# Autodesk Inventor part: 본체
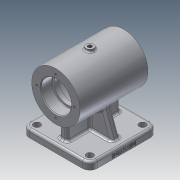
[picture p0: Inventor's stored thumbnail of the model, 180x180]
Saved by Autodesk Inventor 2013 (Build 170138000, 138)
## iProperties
Created: 2019-06
Part Number: 본체
Material: 알루미늄 6061
Document SubType Name: Modeling
Designer: user
Density: 2.71 g/cm^3
Mass: 612.592 g
Surface Area: 621.749 cm^2
Volume: 226.049 cm^3
Author: user
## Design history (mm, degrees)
sketch "스케치1"
  geometry: C1 r 32 at (0, 0); 1 further point
  constraints: 1 centre point, 1 coincident
  dimensions: "d0" = 64 diameter of C1
extrude "돌출1" new body sketch "스케치1" stored distance "d1" = 90; taper "d2" = 0 deg
sketch "스케치2"
  geometry: L1 (32, 45)-(-32, 45) reference; L2 (-32, -45)-(32, -45) reference; L3 (0, 45)-(0, -45); L4 (20, 45)-(20, 30); L5 (20, 30)-(17, 30); L6 (17, 30)-(17, 24); L7 (17, 24)-(25, 24); L8 (25, 24)-(25, -24); L9 (25, -24)-(17, -24); L10 (17, -24)-(17, -30); L11 (17, -30)-(20, -30); L12 (20, -30)-(20, -45); 1 further point
  constraints: 20 end point, 5 perpendicular, 4 parallel, 2 midpoint, 2 point on line
  dimensions: "d3" = 15 distance of L4.start L4.end; "d5" = 15 distance of L11.end L12.end; "d6" = 6 distance of L5.end L6.end; "d7" = 6 distance of L9.end L10.end; "d8" = 40 diameter of L4 L3; "d9" = 40 diameter of L12 L3; "d10" = 50 diameter of L8 L3; "d11" = 34 diameter of L6 L3; "d12" = 34 diameter of L10 L3
revolve "회전1" sketch "스케치2" stored, may be unused: angle "d13" = 90 deg
chamfer "모따기1" distance "d14" = 1; stored, may be unused: second distance "d15" = 2, angle "d16" = 45 deg
fillet "모깎기1" dims "d17" = 3
fillet "모깎기2" dims "d18" = 0.6
sketch "스케치3"
  geometry: L1 (0, 0)-(0, 25); C1 r 21 at (0, 0) reference; 1 further point
  constraints: 2 end point, 1 coincident, 1 vertical
  dimensions: "d19" = 25 distance of L1.start L1.end
hole "구멍1" sketch "스케치3" at (0, 25) diameter "d20" = 3.242; stored, may be unused: countersink angle "d24" = 90 deg, drill point angle "d26" = 118 deg; dims "d21" = 7, "d22" = 4, "d23" = 2, "d25" = 9
node "작업 평면1"
sketch "스케치4"
  geometry: L1 (45, -45)-(-45, -45); L2 (-45, -45)-(-45, 45); L3 (-45, 45)-(45, 45); L4 (45, 45)-(45, -45); L5 (45, -45)-(-45, 45); L6 (-45, -45)-(45, 45); 1 further point
  constraints: 12 end point, 2 midpoint, 2 parallel, 1 horizontal, 1 perpendicular
  dimensions: "d31" = 90 distance of L2.end L3.end; "d32" = 90 distance of L1.end L2.end
extrude "돌출2" join sketch "스케치4" distance "d33" = 10; taper "d34" = 0 deg
fillet "모깎기3" dims "d35" = 10
sketch "스케치5"
  geometry: A1 r 10 centre (-35, -35) between (-45, -35) and (-35, -45) reference; A2 r 10 centre (35, -35) between (35, -45) and (45, -35) reference; A3 r 10 centre (35, 35) between (45, 35) and (35, 45) reference; A4 r 10 centre (-35, 35) between (-35, 45) and (-45, 35) reference; 5 further points
  constraints: 4 coincident
hole "구멍2" sketch "스케치5" at (-35, 35), (35, 35), (35, -35), (-35, -35) diameter "d36" = 9; stored, may be unused: countersink angle "d40" = 90 deg, drill point angle "d42" = 118 deg; dims "d37" = 7, "d38" = 4, "d39" = 2, "d41" = 9
sketch "스케치6"
  geometry: L1 (5, -35)-(-5, -35); L2 (-5, -35)-(-5, 35); L3 (-5, 35)-(5, 35); L4 (5, 35)-(5, -35); L5 (5, -35)-(-5, 35); L6 (-5, -35)-(5, 35); 1 further point
  constraints: 12 end point, 2 midpoint, 2 parallel, 1 horizontal, 1 perpendicular
  dimensions: "d43" = 10 distance of L2.end L3.end; "d44" = 70 distance of L1.end L2.end
extrude "돌출3" join sketch "스케치6" stored distance "d45" = 10; taper "d46" = 0 deg
sketch "스케치7"
  geometry: L1 (35, -55)-(-35, -55) reference; L2 (23.058, -22.189)-(35, -55); L3 (45, -55)-(45, -65) reference; 2 further points
  constraints: 2 end point, 1 point on line, 2 other
  dimensions: "d47" = 110 deg angle of L1 L2; "d48" = 10 distance of L3.start L2.end
feature "리브1" sketch "스케치7" dims "d49" = 1, "d50" = 10, "d51" = 0, "d52" = 0, "d53" = 1, "d54" = 1
node "작업 평면2"
sketch "스케치8"
  geometry: C1 r 5 at (0, 0); 1 further point
  constraints: 1 centre point, 1 coincident
  dimensions: "d56" = 10 diameter of C1
extrude "돌출4" join sketch "스케치8" stored distance "d57" = 10; taper "d58" = 0 deg
sketch "스케치9"
  geometry: C1 r 5 at (0, 0) reference; 1 further point
  constraints: 1 coincident
hole "구멍3" sketch "스케치9" at (0, 0) diameter "d59" = 5.188; stored, may be unused: countersink angle "d63" = 90 deg, drill point angle "d65" = 118 deg; dims "d60" = 20, "d61" = 4, "d62" = 2, "d64" = 9
fillet "모깎기4" dims "d66" = 2
sketch "스케치11"
  geometry: L1 (40, -40)-(-40, -40); L2 (-40, -40)-(-40, 40); L3 (-40, 40)-(40, 40); L4 (40, 40)-(40, -40); C1 r 4.5 at (-35, 35) reference; C2 r 4.5 at (35, -35) reference; C3 r 4.5 at (-35, -35) reference; C4 r 4.5 at (35, 35) reference; 3 further points
  constraints: 8 end point, 2 midpoint, 2 parallel, 1 horizontal, 1 horizontal alignment, 1 perpendicular, 1 vertical alignment
  dimensions: "d73" = 80 distance of L2.end L3.end; "d74" = 80 distance of L1.end L2.end
extrude "돌출5" cut sketch "스케치11" distance "d76" = 5; taper "d77" = 0 deg
sketch "스케치12"
  geometry: C1 r 4.5 at (35, 35) reference; C2 r 4.5 at (-35, -35) reference; C3 r 4.5 at (35, -35) reference; C4 r 4.5 at (-35, 35) reference; C5 r 10 at (35, -35); C6 r 10 at (-35, -35); C7 r 10 at (-35, 35); C8 r 10 at (35, 35); 1 further point
  constraints: 4 centre point, 4 coincident
  dimensions: "d78" = 20 diameter of C5; "d79" = 20 diameter of C6; "d80" = 20 diameter of C7; "d81" = 20 diameter of C8
extrude "돌출6" join sketch "스케치12" distance "d82" = 5; taper "d83" = 0 deg
fillet "모깎기5" dims "d84" = 3
fillet "모깎기6" dims "d85" = 3
fillet "모깎기7" dims "d86" = 3
fillet "모깎기8" dims "d87" = 3
fillet "모깎기9" dims "d88" = 3
sketch "스케치13"
  geometry: L1 (0, 0)-(-10, 0) reference; 2 further points
  constraints: 1 other
  dimensions: "d89" = 4 vertical distance of point (35, 4) L1.end; "d90" = 45 horizontal distance of point (35, 4) L1.end
feature "엠보싱1" sketch "스케치13" dims "d91" = 0.5, "d92" = 0
node "솔리드1"
pattern_circular "원형 패턴1" dims angle "d28" = 360 deg
mirror "대칭1"
mirror "대칭2"
other parameters: "d30" = -65
